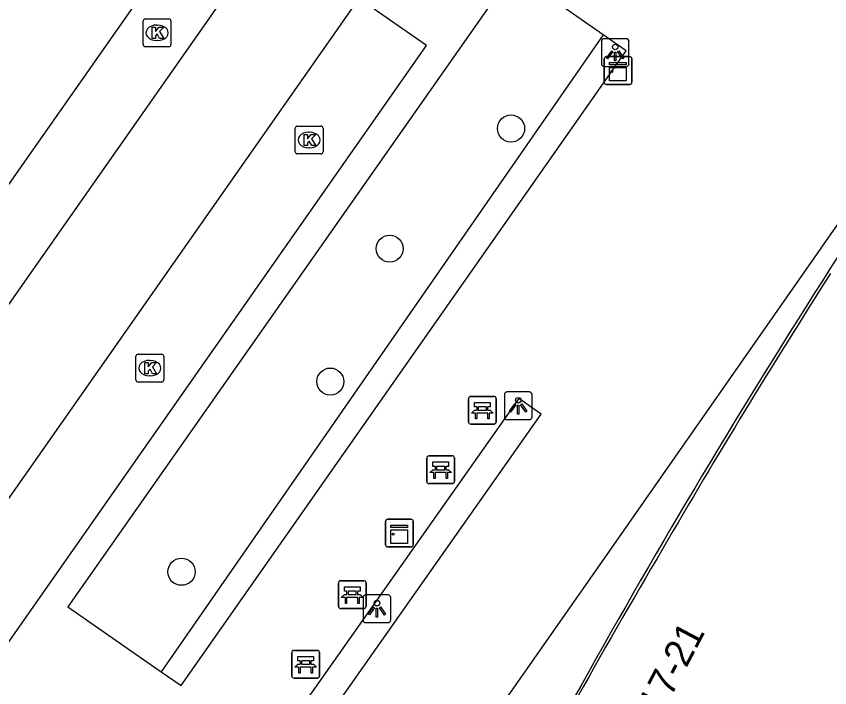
# Model space of a CAD drawing. Extents: x 152881 to 155736, y 382924 to 386919.
# Drawn here: x 155297.9 to 155327.22, y 385319.31 to 385343.5 of the extents above; entities that cross this region are included whole.
import ezdxf

# ---------------------------------------------------------------- set-up
doc = ezdxf.new("R2010")
doc.units = 0
for name, color, linetype in [('IMGEO_Bank', 7, 'Continuous'), ('IMGEO_Boom', 7, 'Continuous'), ('IMGEO_Haag', 7, 'Continuous'), ('IMGEO_Kast', 7, 'Continuous'), ('IMGEO_Kolk', 7, 'Continuous'), ('IMGEO_Lichtpunt', 7, 'Continuous'), ('IMGEO_Lijnafwatering', 7, 'Continuous'), ('IMGEO_Pand', 7, 'Continuous'), ('IMGEO_Pand_nummerreeks', 7, 'Continuous'), ('IMGEO_Pand_overbouw', 7, 'Continuous'), ('IMGEO_Voetpad_open', 7, 'Continuous')]:
    doc.layers.add(name, color=color, linetype=linetype)

msp = doc.modelspace()

# ---------------------------------------------------------------- linework, layer by layer
at = {"layer": 'IMGEO_Bank'}
for p, q in [((155314.276, 385329.808), (155315.117, 385329.808)), ((155315.117, 385329.808), (155314.276, 385329.808)), ((155314.201, 385328.883), (155314.201, 385329.724)), ((155314.201, 385329.724), (155314.201, 385328.883)), ((155315.201, 385329.733), (155315.201, 385328.892)), ((155315.201, 385328.892), (155315.201, 385329.733)), ((155314.51, 385329.314), (155314.51, 385329.42)), ((155314.554, 385329.42), (155314.554, 385329.314)), ((155314.842, 385329.426), (155314.56, 385329.426)), ((155314.56, 385329.308), (155314.842, 385329.308)), ((155314.848, 385329.314), (155314.848, 385329.42)), ((155314.892, 385329.42), (155314.892, 385329.314)), ((155314.898, 385329.206), (155314.505, 385329.206)), ((155315.126, 385328.808), (155314.285, 385328.808)), ((155314.285, 385328.808), (155315.126, 385328.808)), ((155312.698, 385326.739), (155312.698, 385327.58)), ((155312.698, 385327.58), (155312.698, 385326.739)), ((155312.773, 385327.664), (155313.614, 385327.664)), ((155313.614, 385327.664), (155312.773, 385327.664)), ((155313.698, 385327.589), (155313.698, 385326.748)), ((155313.698, 385326.748), (155313.698, 385327.589)), ((155313.007, 385327.17), (155313.007, 385327.276)), ((155313.051, 385327.276), (155313.051, 385327.17)), ((155313.339, 385327.282), (155313.057, 385327.282)), ((155313.057, 385327.164), (155313.339, 385327.164)), ((155313.345, 385327.17), (155313.345, 385327.276)), ((155313.389, 385327.276), (155313.389, 385327.17)), ((155313.395, 385327.062), (155313.002, 385327.062)), ((155313.623, 385326.664), (155312.782, 385326.664)), ((155312.782, 385326.664), (155313.623, 385326.664)), ((155309.511, 385322.24), (155309.511, 385323.081)), ((155309.511, 385323.081), (155309.511, 385322.24)), ((155309.586, 385323.165), (155310.427, 385323.165)), ((155310.427, 385323.165), (155309.586, 385323.165)), ((155310.511, 385323.09), (155310.511, 385322.249)), ((155310.511, 385322.249), (155310.511, 385323.09)), ((155309.82, 385322.671), (155309.82, 385322.777)), ((155309.864, 385322.777), (155309.864, 385322.671)), ((155310.152, 385322.783), (155309.87, 385322.783)), ((155310.158, 385322.671), (155310.158, 385322.777)), ((155310.202, 385322.777), (155310.202, 385322.671)), ((155310.208, 385322.563), (155309.815, 385322.563)), ((155309.87, 385322.665), (155310.152, 385322.665)), ((155310.436, 385322.165), (155309.595, 385322.165)), ((155309.595, 385322.165), (155310.436, 385322.165)), ((155307.831, 385319.731), (155307.831, 385320.572)), ((155307.831, 385320.572), (155307.831, 385319.731)), ((155307.906, 385320.656), (155308.747, 385320.656)), ((155308.747, 385320.656), (155307.906, 385320.656)), ((155308.831, 385320.581), (155308.831, 385319.74)), ((155308.831, 385319.74), (155308.831, 385320.581)), ((155308.14, 385320.162), (155308.14, 385320.268)), ((155308.184, 385320.268), (155308.184, 385320.162)), ((155308.472, 385320.274), (155308.19, 385320.274)), ((155308.19, 385320.156), (155308.472, 385320.156)), ((155308.478, 385320.162), (155308.478, 385320.268)), ((155308.522, 385320.268), (155308.522, 385320.162)), ((155308.528, 385320.054), (155308.135, 385320.054)), ((155308.756, 385319.656), (155307.915, 385319.656)), ((155307.915, 385319.656), (155308.756, 385319.656))]:
    msp.add_line(p, q, dxfattribs=at)
for points in [[(155314.504, 385329.426), (155314.418, 385329.426), (155314.418, 385329.587), (155314.981, 385329.587), (155314.981, 385329.426), (155314.898, 385329.426)], [(155314.448, 385329.206), (155314.306, 385329.206), (155314.418, 385329.308), (155314.504, 385329.308)], [(155314.898, 385329.308), (155314.981, 385329.308), (155315.093, 385329.206), (155314.954, 385329.206)], [(155314.498, 385329.199), (155314.498, 385328.992), (155314.455, 385328.992), (155314.455, 385329.199)], [(155314.948, 385329.199), (155314.948, 385328.992), (155314.904, 385328.992), (155314.904, 385329.199)], [(155312.945, 385327.062), (155312.803, 385327.062), (155312.915, 385327.164), (155313.001, 385327.164)], [(155313.001, 385327.282), (155312.915, 385327.282), (155312.915, 385327.443), (155313.478, 385327.443), (155313.478, 385327.282), (155313.395, 385327.282)], [(155313.395, 385327.164), (155313.478, 385327.164), (155313.59, 385327.062), (155313.451, 385327.062)], [(155312.995, 385327.055), (155312.995, 385326.848), (155312.952, 385326.848), (155312.952, 385327.055)], [(155313.445, 385327.055), (155313.445, 385326.848), (155313.401, 385326.848), (155313.401, 385327.055)], [(155309.814, 385322.783), (155309.728, 385322.783), (155309.728, 385322.944), (155310.291, 385322.944), (155310.291, 385322.783), (155310.208, 385322.783)], [(155309.758, 385322.563), (155309.616, 385322.563), (155309.728, 385322.665), (155309.814, 385322.665)], [(155309.808, 385322.556), (155309.808, 385322.349), (155309.765, 385322.349), (155309.765, 385322.556)], [(155310.208, 385322.665), (155310.291, 385322.665), (155310.403, 385322.563), (155310.264, 385322.563)], [(155310.258, 385322.556), (155310.258, 385322.349), (155310.214, 385322.349), (155310.214, 385322.556)], [(155308.134, 385320.274), (155308.048, 385320.274), (155308.048, 385320.435), (155308.611, 385320.435), (155308.611, 385320.274), (155308.528, 385320.274)], [(155308.078, 385320.054), (155307.936, 385320.054), (155308.048, 385320.156), (155308.134, 385320.156)], [(155308.528, 385320.156), (155308.611, 385320.156), (155308.723, 385320.054), (155308.584, 385320.054)], [(155308.128, 385320.047), (155308.128, 385319.84), (155308.085, 385319.84), (155308.085, 385320.047)], [(155308.578, 385320.047), (155308.578, 385319.84), (155308.534, 385319.84), (155308.534, 385320.047)]]:
    msp.add_lwpolyline(points, dxfattribs=at)
for centre, radius, start, end in [((155314.279, 385329.73), 0.0779, 92.4484, 184.2845), ((155314.279, 385329.73), 0.0779, 92.4484, 184.2845), ((155315.123, 385329.73), 0.0779, 2.4484, 94.2845), ((155315.123, 385329.73), 0.0779, 2.4484, 94.2845), ((155314.503, 385329.419), 0.00671, 2.8957, 87.1043), ((155314.503, 385329.315), 0.00671, 272.8957, 357.1043), ((155314.56, 385329.419), 0.00671, 92.8957, 177.1043), ((155314.56, 385329.315), 0.00671, 182.8957, 267.1043), ((155314.842, 385329.419), 0.00671, 2.8957, 87.1043), ((155314.842, 385329.315), 0.00671, 272.8957, 357.1043), ((155314.899, 385329.419), 0.00671, 92.8957, 177.1043), ((155314.899, 385329.315), 0.00671, 182.8957, 267.1043), ((155314.448, 385329.199), 0.00671, 2.8957, 87.1043), ((155314.505, 385329.199), 0.00671, 92.8957, 177.1043), ((155314.897, 385329.199), 0.00671, 2.8957, 87.1043), ((155314.954, 385329.199), 0.00671, 92.8957, 177.1043), ((155314.279, 385328.886), 0.0779, 182.4484, 274.2845), ((155314.279, 385328.886), 0.0779, 182.4484, 274.2845), ((155315.123, 385328.886), 0.0779, 272.4484, 4.2845), ((155315.123, 385328.886), 0.0779, 272.4484, 4.2845), ((155312.776, 385327.586), 0.0779, 92.4484, 184.2845), ((155312.776, 385327.586), 0.0779, 92.4484, 184.2845), ((155313.62, 385327.586), 0.0779, 2.4484, 94.2845), ((155313.62, 385327.586), 0.0779, 2.4484, 94.2845), ((155313, 385327.275), 0.00671, 2.8957, 87.1043), ((155313, 385327.171), 0.00671, 272.8957, 357.1043), ((155313.057, 385327.275), 0.00671, 92.8957, 177.1043), ((155313.057, 385327.171), 0.00671, 182.8957, 267.1043), ((155313.339, 385327.275), 0.00671, 2.8957, 87.1043), ((155313.339, 385327.171), 0.00671, 272.8957, 357.1043), ((155313.396, 385327.275), 0.00671, 92.8957, 177.1043), ((155313.396, 385327.171), 0.00671, 182.8957, 267.1043), ((155312.945, 385327.055), 0.00671, 2.8957, 87.1043), ((155313.002, 385327.055), 0.00671, 92.8957, 177.1043), ((155313.394, 385327.055), 0.00671, 2.8957, 87.1043), ((155313.451, 385327.055), 0.00671, 92.8957, 177.1043), ((155312.776, 385326.742), 0.0779, 182.4484, 274.2845), ((155312.776, 385326.742), 0.0779, 182.4484, 274.2845), ((155313.62, 385326.742), 0.0779, 272.4484, 4.2845), ((155313.62, 385326.742), 0.0779, 272.4484, 4.2845), ((155309.589, 385323.087), 0.0779, 92.4484, 184.2845), ((155309.589, 385323.087), 0.0779, 92.4484, 184.2845), ((155310.433, 385323.087), 0.0779, 2.4484, 94.2845), ((155310.433, 385323.087), 0.0779, 2.4484, 94.2845), ((155309.813, 385322.776), 0.00671, 2.8957, 87.1043), ((155309.87, 385322.776), 0.00671, 92.8957, 177.1043), ((155310.152, 385322.776), 0.00671, 2.8957, 87.1043), ((155310.209, 385322.776), 0.00671, 92.8957, 177.1043), ((155309.758, 385322.556), 0.00671, 2.8957, 87.1043), ((155309.815, 385322.556), 0.00671, 92.8957, 177.1043), ((155309.813, 385322.672), 0.00671, 272.8957, 357.1043), ((155309.87, 385322.672), 0.00671, 182.8957, 267.1043), ((155310.152, 385322.672), 0.00671, 272.8957, 357.1043), ((155310.209, 385322.672), 0.00671, 182.8957, 267.1043), ((155310.207, 385322.556), 0.00671, 2.8957, 87.1043), ((155310.264, 385322.556), 0.00671, 92.8957, 177.1043), ((155309.589, 385322.243), 0.0779, 182.4484, 274.2845), ((155309.589, 385322.243), 0.0779, 182.4484, 274.2845), ((155310.433, 385322.243), 0.0779, 272.4484, 4.2845), ((155310.433, 385322.243), 0.0779, 272.4484, 4.2845), ((155307.909, 385320.578), 0.0779, 92.4484, 184.2845), ((155307.909, 385320.578), 0.0779, 92.4484, 184.2845), ((155308.753, 385320.578), 0.0779, 2.4484, 94.2845), ((155308.753, 385320.578), 0.0779, 2.4484, 94.2845), ((155308.133, 385320.267), 0.00671, 2.8957, 87.1043), ((155308.133, 385320.163), 0.00671, 272.8957, 357.1043), ((155308.19, 385320.267), 0.00671, 92.8957, 177.1043), ((155308.19, 385320.163), 0.00671, 182.8957, 267.1043), ((155308.472, 385320.267), 0.00671, 2.8957, 87.1043), ((155308.472, 385320.163), 0.00671, 272.8957, 357.1043), ((155308.529, 385320.267), 0.00671, 92.8957, 177.1043), ((155308.529, 385320.163), 0.00671, 182.8957, 267.1043), ((155308.078, 385320.047), 0.00671, 2.8957, 87.1043), ((155308.135, 385320.047), 0.00671, 92.8957, 177.1043), ((155308.527, 385320.047), 0.00671, 2.8957, 87.1043), ((155308.584, 385320.047), 0.00671, 92.8957, 177.1043), ((155307.909, 385319.734), 0.0779, 182.4484, 274.2845), ((155307.909, 385319.734), 0.0779, 182.4484, 274.2845), ((155308.753, 385319.734), 0.0779, 272.4484, 4.2845), ((155308.753, 385319.734), 0.0779, 272.4484, 4.2845)]:
    msp.add_arc(centre, radius, start, end, dxfattribs=at)
at = {"layer": 'IMGEO_Boom'}
for centre in [(155315.736, 385339.458), (155311.36, 385335.129), (155309.221, 385330.339), (155303.858, 385323.488)]:
    msp.add_circle(centre, 0.489, dxfattribs=at)
at = {"layer": 'IMGEO_Haag'}
msp.add_lwpolyline([(155319.053, 385342.837), (155303.124, 385319.88)], dxfattribs=at)
at = {"layer": 'IMGEO_Kast'}
for p, q in [((155319.092, 385341.122), (155319.092, 385341.963)), ((155319.092, 385341.963), (155319.092, 385341.122)), ((155319.167, 385342.047), (155320.008, 385342.047)), ((155320.008, 385342.047), (155319.167, 385342.047)), ((155320.092, 385341.972), (155320.092, 385341.131)), ((155320.092, 385341.131), (155320.092, 385341.972)), ((155320.017, 385341.047), (155319.176, 385341.047)), ((155319.176, 385341.047), (155320.017, 385341.047)), ((155311.21, 385324.456), (155311.21, 385325.297)), ((155311.21, 385325.297), (155311.21, 385324.456)), ((155311.285, 385325.381), (155312.126, 385325.381)), ((155312.126, 385325.381), (155311.285, 385325.381)), ((155312.21, 385325.306), (155312.21, 385324.465)), ((155312.21, 385324.465), (155312.21, 385325.306)), ((155312.135, 385324.381), (155311.294, 385324.381)), ((155311.294, 385324.381), (155312.135, 385324.381))]:
    msp.add_line(p, q, dxfattribs=at)
for points in [[(155319.287, 385341.837), (155319.887, 385341.837), (155319.887, 385341.752), (155319.287, 385341.752), (155319.287, 385341.837)], [(155319.287, 385341.662), (155319.887, 385341.662), (155319.887, 385341.173), (155319.287, 385341.173), (155319.287, 385341.662)], [(155311.405, 385325.171), (155312.005, 385325.171), (155312.005, 385325.086), (155311.405, 385325.086), (155311.405, 385325.171)], [(155311.405, 385324.996), (155312.005, 385324.996), (155312.005, 385324.507), (155311.405, 385324.507), (155311.405, 385324.996)]]:
    msp.add_lwpolyline(points, dxfattribs=at)
for centre in [(155319.371, 385341.511), (155311.489, 385324.845)]:
    msp.add_circle(centre, 0.0377, dxfattribs=at)
for centre, start, end in [((155319.17, 385341.969), 92.4484, 184.2845), ((155319.17, 385341.969), 92.4484, 184.2845), ((155320.014, 385341.969), 2.4484, 94.2845), ((155320.014, 385341.969), 2.4484, 94.2845), ((155319.17, 385341.125), 182.4484, 274.2845), ((155319.17, 385341.125), 182.4484, 274.2845), ((155320.014, 385341.125), 272.4484, 4.2845), ((155320.014, 385341.125), 272.4484, 4.2845), ((155311.288, 385325.303), 92.4484, 184.2845), ((155311.288, 385325.303), 92.4484, 184.2845), ((155312.132, 385325.303), 2.4484, 94.2845), ((155312.132, 385325.303), 2.4484, 94.2845), ((155311.288, 385324.459), 182.4484, 274.2845), ((155311.288, 385324.459), 182.4484, 274.2845), ((155312.132, 385324.459), 272.4484, 4.2845), ((155312.132, 385324.459), 272.4484, 4.2845)]:
    msp.add_arc(centre, 0.0779, start, end, dxfattribs=at)
at = {"layer": 'IMGEO_Kolk'}
for p, q in [((155302.475, 385342.48), (155302.475, 385343.332)), ((155302.55, 385343.406), (155303.402, 385343.406)), ((155303.476, 385343.332), (155303.476, 385342.48)), ((155302.963, 385343.186), (155302.988, 385343.186)), ((155302.986, 385342.626), (155302.961, 385342.626)), ((155303.402, 385342.406), (155302.55, 385342.406)), ((155308.031, 385339.543), (155308.883, 385339.543)), ((155307.956, 385338.617), (155307.956, 385339.469)), ((155308.444, 385339.323), (155308.469, 385339.323)), ((155308.957, 385339.469), (155308.957, 385338.617)), ((155308.467, 385338.763), (155308.442, 385338.763)), ((155308.883, 385338.543), (155308.031, 385338.543)), ((155302.289, 385331.324), (155303.141, 385331.324)), ((155302.214, 385330.398), (155302.214, 385331.25)), ((155302.702, 385331.104), (155302.727, 385331.104)), ((155303.215, 385331.25), (155303.215, 385330.398)), ((155302.725, 385330.544), (155302.7, 385330.544)), ((155303.141, 385330.324), (155302.289, 385330.324))]:
    msp.add_line(p, q, dxfattribs=at)
for points in [[(155302.475, 385342.48), (155302.475, 385343.332)], [(155302.55, 385343.406), (155303.402, 385343.406)], [(155303.476, 385343.332), (155303.476, 385342.48)], [(155302.796, 385343.106), (155302.919, 385343.106), (155302.919, 385342.955), (155303.049, 385343.106), (155303.213, 385343.106), (155303.067, 385342.955), (155303.22, 385342.706), (155303.068, 385342.706), (155302.983, 385342.87), (155302.919, 385342.803), (155302.919, 385342.706), (155302.796, 385342.706), (155302.796, 385343.106)], [(155303.402, 385342.406), (155302.55, 385342.406)], [(155308.031, 385339.543), (155308.883, 385339.543)], [(155307.956, 385338.617), (155307.956, 385339.469)], [(155308.277, 385339.243), (155308.4, 385339.243), (155308.4, 385339.092), (155308.53, 385339.243), (155308.694, 385339.243), (155308.548, 385339.092), (155308.701, 385338.843), (155308.549, 385338.843), (155308.464, 385339.007), (155308.4, 385338.94), (155308.4, 385338.843), (155308.277, 385338.843), (155308.277, 385339.243)], [(155308.957, 385339.469), (155308.957, 385338.617)], [(155308.883, 385338.543), (155308.031, 385338.543)], [(155302.289, 385331.324), (155303.141, 385331.324)], [(155302.214, 385330.398), (155302.214, 385331.25)], [(155302.535, 385331.024), (155302.658, 385331.024), (155302.658, 385330.873), (155302.788, 385331.024), (155302.952, 385331.024), (155302.806, 385330.873), (155302.959, 385330.624), (155302.807, 385330.624), (155302.722, 385330.788), (155302.658, 385330.721), (155302.658, 385330.624), (155302.535, 385330.624), (155302.535, 385331.024)], [(155303.215, 385331.25), (155303.215, 385330.398)], [(155303.141, 385330.324), (155302.289, 385330.324)]]:
    msp.add_lwpolyline(points, dxfattribs=at)
for centre, start, end in [((155302.552, 385343.33), 91.552, 178.448), ((155302.552, 385343.33), 91.552, 178.448), ((155303.4, 385343.33), 1.552, 88.448), ((155303.4, 385343.33), 1.552, 88.448), ((155302.552, 385342.482), 181.552, 268.448), ((155302.552, 385342.482), 181.552, 268.448), ((155303.4, 385342.482), 271.552, 358.448), ((155303.4, 385342.482), 271.552, 358.448), ((155308.033, 385339.467), 91.552, 178.448), ((155308.033, 385339.467), 91.552, 178.448), ((155308.881, 385339.467), 1.552, 88.448), ((155308.881, 385339.467), 1.552, 88.448), ((155308.033, 385338.619), 181.552, 268.448), ((155308.033, 385338.619), 181.552, 268.448), ((155308.881, 385338.619), 271.552, 358.448), ((155308.881, 385338.619), 271.552, 358.448), ((155302.291, 385331.248), 91.552, 178.448), ((155302.291, 385331.248), 91.552, 178.448), ((155303.139, 385331.248), 1.552, 88.448), ((155303.139, 385331.248), 1.552, 88.448), ((155302.291, 385330.4), 181.552, 268.448), ((155302.291, 385330.4), 181.552, 268.448), ((155303.139, 385330.4), 271.552, 358.448), ((155303.139, 385330.4), 271.552, 358.448)]:
    msp.add_arc(centre, 0.0765, start, end, dxfattribs=at)
for centre, major_axis, ratio, start_param, end_param in [((155302.962, 385342.906), (-0.387, 0.002), 0.722429, 4.712389, 7.853982), ((155302.987, 385342.906), (-0.39, 0.002), 0.717154, 1.570796, 4.712389), ((155308.443, 385339.043), (-0.387, 0.002), 0.722429, 4.712389, 7.853982), ((155308.468, 385339.043), (-0.39, 0.002), 0.717154, 1.570796, 4.712389), ((155302.701, 385330.824), (-0.387, 0.002), 0.722429, 4.712389, 7.853982), ((155302.726, 385330.824), (-0.39, 0.002), 0.717154, 1.570796, 4.712389)]:
    msp.add_ellipse(centre, major_axis=major_axis, ratio=ratio, start_param=start_param, end_param=end_param, dxfattribs=at)
at = {"layer": 'IMGEO_Lichtpunt'}
for p, q in [((155318.992, 385342.597), (155318.992, 385341.79)), ((155318.992, 385342.597), (155318.992, 385341.79)), ((155319.894, 385342.692), (155319.086, 385342.692)), ((155319.894, 385342.692), (155319.086, 385342.692)), ((155319.988, 385341.79), (155319.988, 385342.597)), ((155319.988, 385341.79), (155319.988, 385342.597)), ((155319.086, 385341.696), (155319.894, 385341.696)), ((155319.086, 385341.696), (155319.894, 385341.696)), ((155315.496, 385329.87), (155315.496, 385329.063)), ((155315.496, 385329.87), (155315.496, 385329.063)), ((155316.398, 385329.965), (155315.59, 385329.965)), ((155316.398, 385329.965), (155315.59, 385329.965)), ((155316.492, 385329.063), (155316.492, 385329.87)), ((155316.492, 385329.063), (155316.492, 385329.87)), ((155315.59, 385328.969), (155316.398, 385328.969)), ((155315.59, 385328.969), (155316.398, 385328.969)), ((155310.403, 385322.557), (155310.403, 385321.75)), ((155310.403, 385322.557), (155310.403, 385321.75)), ((155311.305, 385322.652), (155310.497, 385322.652)), ((155311.305, 385322.652), (155310.497, 385322.652)), ((155311.399, 385321.75), (155311.399, 385322.557)), ((155311.399, 385321.75), (155311.399, 385322.557)), ((155310.497, 385321.656), (155311.305, 385321.656)), ((155310.497, 385321.656), (155311.305, 385321.656))]:
    msp.add_line(p, q, dxfattribs=at)
for points in [[(155319.366, 385342.261), (155319.405, 385342.233), (155319.217, 385341.971), (155319.179, 385341.998), (155319.366, 385342.261)], [(155319.468, 385342.213), (155319.515, 385342.213), (155319.515, 385341.891), (155319.468, 385341.891), (155319.468, 385342.213)], [(155319.578, 385342.233), (155319.616, 385342.26), (155319.803, 385341.998), (155319.764, 385341.97), (155319.578, 385342.233)], [(155315.87, 385329.534), (155315.909, 385329.506), (155315.721, 385329.244), (155315.683, 385329.271), (155315.87, 385329.534)], [(155316.082, 385329.506), (155316.12, 385329.533), (155316.307, 385329.271), (155316.268, 385329.243), (155316.082, 385329.506)], [(155315.972, 385329.486), (155316.019, 385329.486), (155316.019, 385329.164), (155315.972, 385329.164), (155315.972, 385329.486)], [(155310.777, 385322.221), (155310.816, 385322.193), (155310.628, 385321.931), (155310.59, 385321.958), (155310.777, 385322.221)], [(155310.879, 385322.173), (155310.926, 385322.173), (155310.926, 385321.851), (155310.879, 385321.851), (155310.879, 385322.173)], [(155310.989, 385322.193), (155311.027, 385322.22), (155311.214, 385321.958), (155311.175, 385321.93), (155310.989, 385322.193)]]:
    msp.add_lwpolyline(points, dxfattribs=at)
for centre in [(155319.491, 385342.395), (155315.995, 385329.668), (155310.902, 385322.355)]:
    msp.add_circle(centre, 0.0994, dxfattribs=at)
for centre, start, end in [((155319.086, 385342.597), 90, 180), ((155319.086, 385342.597), 90, 180), ((155319.894, 385342.597), 0, 90), ((155319.894, 385342.597), 0, 90), ((155319.086, 385341.79), 180, 270), ((155319.086, 385341.79), 180, 270), ((155319.894, 385341.79), 270, 0), ((155319.894, 385341.79), 270, 360), ((155315.59, 385329.87), 90, 180), ((155315.59, 385329.87), 90, 180), ((155316.398, 385329.87), 0, 90), ((155316.398, 385329.87), 0, 90), ((155315.59, 385329.063), 180, 270), ((155315.59, 385329.063), 180, 270), ((155316.398, 385329.063), 270, 0), ((155316.398, 385329.063), 270, 360), ((155310.497, 385322.557), 90, 180), ((155310.497, 385322.557), 90, 180), ((155311.305, 385322.557), 0, 90), ((155311.305, 385322.557), 0, 90), ((155310.497, 385321.75), 180, 270), ((155310.497, 385321.75), 180, 270), ((155311.305, 385321.75), 270, 0), ((155311.305, 385321.75), 270, 360)]:
    msp.add_arc(centre, 0.0946, start, end, dxfattribs=at)
at = {"layer": 'IMGEO_Lijnafwatering'}
for points in [[(155319.366, 385324.353), (155330.346, 385340.046)], [(155308.386, 385308.66), (155319.366, 385324.353)]]:
    msp.add_lwpolyline(points, dxfattribs=at)
at = {"layer": 'IMGEO_Pand'}
for centre, radius, start, end in [((155559.453, 385185.889), 275.544, 147.42843, 149.84119), ((155577.757, 385173.056), 297.824, 149.47577, 152.00529)]:
    msp.add_arc(centre, radius, start, end, dxfattribs=at)
at = {"layer": 'IMGEO_Pand_overbouw'}
for centre, radius, start, end in [((155575.826, 385175.435), 295.073, 146.43584, 149.84345), ((155605.632, 385158.872), 329.166, 149.95696, 153.01624)]:
    msp.add_arc(centre, radius, start, end, dxfattribs=at)
at = {"layer": 'IMGEO_Voetpad_open'}
for points in [[(155304.947, 385347.899), (155276.822, 385307.808), (155278.866, 385306.377), (155306.977, 385346.465), (155304.947, 385347.899)], [(155319.053, 385342.837), (155315.818, 385345.103), (155299.756, 385322.222), (155303.124, 385319.88)], [(155310.245, 385344.16), (155282.142, 385304.068), (155284.593, 385302.367), (155312.69, 385342.45), (155310.245, 385344.16)], [(155303.124, 385319.88), (155303.838, 385319.384), (155319.885, 385342.255), (155319.053, 385342.837)], [(155316.82, 385329.161), (155316.011, 385329.731), (155307.677, 385317.9), (155308.492, 385317.335), (155316.82, 385329.161)]]:
    msp.add_lwpolyline(points, dxfattribs=at)

# ---------------------------------------------------------------- texts
at = {"layer": 'IMGEO_Pand_nummerreeks'}
msp.add_text('17-21', height=1, rotation=62.2633, dxfattribs=at).set_placement((155321.154, 385318.289))

doc.saveas('drawing.dxf')
